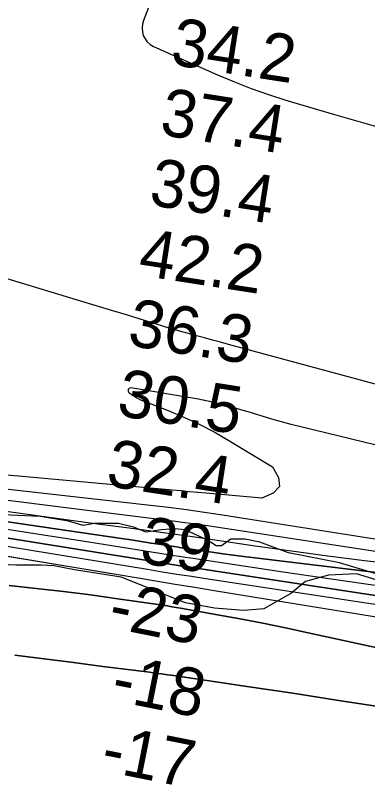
# Model space of a CAD drawing. Extents: x 3192986 to 3230865, y 867483 to 892886.
# Drawn here: x 3210569 to 3211065, y 879751 to 880841 of the extents above; entities that cross this region are included whole.
import ezdxf

# ---------------------------------------------------------------- set-up
doc = ezdxf.new("R2010")
doc.units = 0
for name, color, linetype in [('V-RIVR-EDGE', 7, 'Continuous'), ('V-RIVR-RANG', 7, 'Continuous'), ('V-SITE-VEGE', 7, 'Continuous'), ('V-TOPO-DPTH', 7, 'Continuous'), ('V-TOPO-MAJR', 7, 'Continuous'), ('V-TOPO-MINR', 7, 'Continuous'), ('V-TOPO-WATR', 7, 'Continuous')]:
    doc.layers.add(name, color=color, linetype=linetype)

msp = doc.modelspace()

# ---------------------------------------------------------------- linework, layer by layer
at = {"layer": 'V-RIVR-EDGE'}
for points in [[(3210859.2, 880094.2), (3210851.8, 880094.2), (3210839.7, 880102.5), (3210808.4, 880116.9), (3210793.2, 880118.3), (3210774.9, 880117), (3210753.2, 880113.6), (3210735.4, 880120.6), (3210714.5, 880125.8), (3210680.6, 880125.9), (3210664.5, 880122.9), (3210644.1, 880129.1), (3210604.1, 880135.7), (3210541.1, 880138.4)], [(3211076.9, 880055), (3211025.6, 880070.3), (3210953.5, 880084.4), (3210913.5, 880099.3), (3210892.7, 880103.7), (3210872.7, 880103.7), (3210859.2, 880094.2)]]:
    msp.add_lwpolyline(points, dxfattribs=at)
at = {"layer": 'V-SITE-VEGE'}
msp.add_lwpolyline([(3211090.9, 880042.3), (3211049.3, 880054.9), (3211010.1, 880052.9), (3210977.7, 880044), (3210957, 880027.2), (3210919.2, 880005.6), (3210890.2, 880003.5), (3210849.4, 880006.6), (3210808.6, 880014), (3210718, 880050.2), (3210652.3, 880060.6), (3210623.4, 880066.1), (3210605.5, 880067.2), (3210569.8, 880066.9), (3210528.1, 880069.2)], dxfattribs=at)
at = {"layer": 'V-TOPO-DPTH'}
for points in [[(3210112.9, 880193.6), (3210718.5, 880104.6), (3210732.4, 880102.6), (3210746.4, 880100.5), (3210760.3, 880098.3), (3210774.3, 880096.2), (3210798.9, 880092.4), (3210800.5, 880092.1), (3210803.8, 880091.6), (3210805.5, 880091.4), (3210831.6, 880087.4), (3210846.4, 880085.3), (3210861.1, 880083.2), (3210875.9, 880081.2), (3210890.7, 880079.4), (3211579, 879996.4), (3211581.2, 879996.2), (3211585.7, 879995.6), (3211588, 879995.3), (3211592.5, 879994.7), (3211594.8, 879994.3), (3211597, 879993.9), (3212032, 879904.4), (3212085, 879893.1)], [(3210112.9, 880193.6), (3210718.5, 880104.6), (3210732.4, 880102.6), (3210746.4, 880100.5), (3210760.3, 880098.3), (3210774.3, 880096.2), (3210798.9, 880092.4), (3210800.5, 880092.1), (3210803.8, 880091.6), (3210805.5, 880091.4), (3210831.6, 880087.4), (3210846.4, 880085.3), (3210861.1, 880083.2), (3210875.9, 880081.2), (3210890.7, 880079.4), (3211579, 879996.4), (3211581.2, 879996.2), (3211585.7, 879995.6), (3211588, 879995.3), (3211592.5, 879994.7), (3211594.8, 879994.3), (3211597, 879993.9), (3212032, 879904.4), (3212085, 879893.1)], [(3212100.7, 879932.9), (3212018.6, 879954.3), (3211575.3, 880022.3), (3211415.7, 880040.8), (3211330.7, 880051.1), (3211245.8, 880062), (3211161, 880073.8), (3211076.3, 880086.3), (3210839.6, 880122.3), (3210823.6, 880124.7), (3210807.6, 880126.9), (3210791.5, 880129.1), (3210775.5, 880131.1), (3210651.7, 880146.4), (3210573.7, 880156.1), (3210495.8, 880165.9)], [(3212273.2, 879751.3), (3211940.1, 879826.4), (3211878.8, 879840.2), (3211817.4, 879853.9), (3211756.1, 879867.5), (3211694.7, 879881), (3211644.4, 879892.1), (3211608.1, 879899.9), (3211571.8, 879907.4), (3211535.3, 879914.6), (3211498.9, 879921.5), (3211449.5, 879930.6), (3211388.3, 879941.7), (3211327.1, 879952.5), (3211265.8, 879963), (3211204.4, 879973.2), (3210849.3, 880031.1), (3210821.8, 880035.6), (3210794.3, 880040.1), (3210766.8, 880044.7), (3210739.3, 880049.2), (3210106, 880154.6)], [(3210517.9, 880111.9), (3210769.9, 880071.3), (3210784.1, 880069), (3210798.4, 880066.7), (3210812.6, 880064.5), (3210826.9, 880062.3), (3211177.7, 880009.1), (3211244.6, 879999.2), (3211311.6, 879989.8), (3211378.6, 879981), (3211445.7, 879972.5), (3211578.3, 879956.4), (3211579.1, 879956.3), (3211579.9, 879956.2), (3211584.1, 879955.6), (3211584.9, 879955.4), (3212313.1, 879797.1)], [(3212313.1, 879797.1), (3211584.9, 879955.4), (3211584.1, 879955.6), (3211579.9, 879956.2), (3211579.1, 879956.3), (3211578.3, 879956.4), (3211445.7, 879972.5), (3211378.6, 879981), (3211311.6, 879989.8), (3211244.6, 879999.2), (3211177.7, 880009.1), (3210826.9, 880062.3), (3210812.6, 880064.5), (3210798.4, 880066.7), (3210784.1, 880069), (3210769.9, 880071.3), (3210517.9, 880111.9)], [(3212273.2, 879751.3), (3211940.1, 879826.4), (3211878.8, 879840.2), (3211817.4, 879853.9), (3211756.1, 879867.5), (3211694.7, 879881), (3211644.4, 879892.1), (3211608.1, 879899.9), (3211571.8, 879907.4), (3211535.3, 879914.6), (3211498.9, 879921.5), (3211449.5, 879930.6), (3211388.3, 879941.7), (3211327.1, 879952.5), (3211265.8, 879963), (3211204.4, 879973.2), (3210849.3, 880031.1), (3210821.8, 880035.6), (3210794.3, 880040.1), (3210766.8, 880044.7), (3210739.3, 880049.2), (3210478.2, 880092.7)], [(3210560.5, 880038.3), (3210598.8, 880034.4), (3210637, 880030.1), (3210675.2, 880025.2), (3210713.3, 880019.9), (3210777, 880010.6), (3210783.3, 880009.7), (3210789.5, 880008.7), (3210795.7, 880007.7), (3210801.9, 880006.6), (3210853.6, 879997.4), (3210885.6, 879991.5), (3210917.6, 879985.3), (3210949.4, 879978.8), (3210981.3, 879972.1), (3211546, 879849.6)], [(3211546, 879849.6), (3210981.3, 879972.1), (3210949.4, 879978.8), (3210917.6, 879985.3), (3210885.6, 879991.5), (3210853.6, 879997.4), (3210801.9, 880006.6), (3210795.7, 880007.7), (3210789.5, 880008.7), (3210783.3, 880009.7), (3210777, 880010.6), (3210713.3, 880019.9), (3210675.2, 880025.2), (3210637, 880030.1), (3210598.8, 880034.4), (3210560.5, 880038.3)], [(3211544.4, 879792.6), (3211522, 879795.7), (3211499.7, 879799.2), (3211144.6, 879857.6), (3211083.1, 879867.6), (3211021.5, 879877.3), (3210959.9, 879886.7), (3210898.3, 879896), (3210791.7, 879911.7), (3210783.4, 879912.9), (3210775, 879914.1), (3210766.7, 879915.2), (3210758.3, 879916.3), (3210692.5, 879924.6), (3210651.2, 879929.9), (3210609.9, 879935.2), (3210568.7, 879940.6)], [(3210568.7, 879940.6), (3210609.9, 879935.2), (3210651.2, 879929.9), (3210692.5, 879924.6), (3210758.3, 879916.3), (3210766.7, 879915.2), (3210775, 879914.1), (3210783.4, 879912.9), (3210791.7, 879911.7), (3210898.3, 879896), (3210959.9, 879886.7), (3211021.5, 879877.3), (3211083.1, 879867.6), (3211144.6, 879857.6), (3211499.7, 879799.2), (3211522, 879795.7), (3211544.4, 879792.6)]]:
    msp.add_lwpolyline(points, dxfattribs=at)
at = {"layer": 'V-TOPO-MAJR'}
for points in [[(3210770.7, 880889.3), (3210749.6, 880834), (3210748.2, 880828.7), (3210747.6, 880823.4), (3210748.1, 880818.1), (3210749.4, 880812.8), (3210751.9, 880807.9), (3210755, 880803.7), (3210759, 880800.3), (3210763.6, 880797.5), (3210853.9, 880757.3), (3210877.5, 880747.4), (3210901.3, 880738.1), (3210925.4, 880729.8), (3210949.8, 880722), (3211018.6, 880701.7), (3211077.7, 880684.7)], [(3211190.4, 880290.8), (3210869.3, 880378), (3210858.1, 880381), (3210846.8, 880384), (3210835.6, 880387.1), (3210824.4, 880390.1), (3210813.2, 880393.2), (3210802, 880396.3), (3210790.9, 880399.6), (3210779.7, 880402.9), (3210763.9, 880407.8), (3210744.8, 880413.6), (3210725.8, 880419.4), (3210706.7, 880425.2), (3210687.7, 880430.9), (3210432, 880508.2)]]:
    msp.add_lwpolyline(points, dxfattribs=at)
at = {"layer": 'V-TOPO-MINR'}
for points in [[(3211835.7, 880051.7), (3210957.5, 880265), (3210943.8, 880268.8), (3210930.2, 880272.8), (3210916.7, 880276.8), (3210903.2, 880280.9), (3210896.9, 880282.9), (3210886.5, 880286), (3210876, 880289), (3210865.6, 880291.8), (3210855, 880294.4), (3210840.5, 880298), (3210837.2, 880298.7), (3210833.9, 880299.5), (3210830.6, 880300.1), (3210827.2, 880300.7), (3210732, 880316.6), (3210729.6, 880315.8), (3210728.2, 880314.6), (3210728.2, 880312.7), (3210729.2, 880310.3), (3210734.7, 880306.3), (3210740.4, 880302.7), (3210746.5, 880299.6), (3210752.7, 880296.9), (3210784.5, 880284.7), (3210806.5, 880275.6), (3210828.1, 880265.7), (3210849.1, 880254.7), (3210869.8, 880242.8), (3210931, 880205.6), (3210939.6, 880190.5), (3210941.2, 880177.7), (3210932.3, 880168.4), (3210916.4, 880161.3), (3210837.9, 880168.4), (3210826.1, 880169.4), (3210814.2, 880170.5), (3210802.4, 880171.6), (3210790.5, 880172.7), (3210350.8, 880212.6)], [(3212039.6, 879926.4), (3211960.5, 879943.7), (3211881.2, 879959.8), (3211579.1, 880014.5), (3211111.7, 880067.4), (3211060.5, 880073.4), (3211009.2, 880079.8), (3210958.1, 880086.7), (3210907, 880093.9), (3210818.4, 880106.8), (3210811.6, 880107.8), (3210804.8, 880108.7), (3210798, 880109.7), (3210791.2, 880110.6), (3210729.7, 880119), (3210692.2, 880124.1), (3210654.6, 880129.2), (3210617.1, 880134.4), (3210579.6, 880139.6), (3210103.3, 880206.1)], [(3212354.1, 879878.5), (3211585.8, 880029.7), (3211583.5, 880029.1), (3211581, 880029), (3211518.1, 880036.4), (3211484, 880040.7), (3211449.9, 880045.2), (3211415.9, 880050.1), (3211381.9, 880055.2), (3210860.8, 880137.6), (3210835.6, 880141.4), (3210810.3, 880145), (3210785, 880148.3), (3210759.7, 880151.3), (3210521.7, 880178)], [(3212100.7, 879932.9), (3212018.6, 879954.3), (3211575.3, 880022.3), (3211415.7, 880040.8), (3211330.7, 880051.1), (3211245.8, 880062), (3211161, 880073.8), (3211076.3, 880086.3), (3210839.6, 880122.3), (3210823.6, 880124.7), (3210807.6, 880126.9), (3210791.5, 880129.1), (3210775.5, 880131.1), (3210651.7, 880146.4), (3210573.7, 880156.1), (3210495.8, 880165.9)], [(3212273.2, 879751.3), (3211940.1, 879826.4), (3211878.8, 879840.2), (3211817.4, 879853.9), (3211756.1, 879867.5), (3211694.7, 879881), (3211644.4, 879892.1), (3211608.1, 879899.9), (3211571.8, 879907.4), (3211535.3, 879914.6), (3211498.9, 879921.5), (3211449.5, 879930.6), (3211388.3, 879941.7), (3211327.1, 879952.5), (3211265.8, 879963), (3211204.4, 879973.2), (3210849.3, 880031.1), (3210821.8, 880035.6), (3210794.3, 880040.1), (3210766.8, 880044.7), (3210739.3, 880049.2), (3210106, 880154.6)], [(3212254.4, 879783.6), (3211762.8, 879895.5), (3211732.2, 879902.4), (3211701.5, 879909.3), (3211670.8, 879916.1), (3211640.1, 879922.9), (3211578.9, 879936.3), (3211578.6, 879936.3), (3211577.9, 879936.4), (3211558.9, 879938.7), (3211549.3, 879939.9), (3211539.8, 879941.2), (3211530.2, 879942.6), (3211520.6, 879944), (3210837.5, 880047.8), (3210817, 880051), (3210796.4, 880054.2), (3210775.9, 880057.5), (3210755.4, 880060.8), (3210263.6, 880141.5)], [(3212175.6, 879850), (3211590.9, 879974.6), (3211589.4, 879974.9), (3211586.3, 879975.4), (3211581.7, 879976), (3211580.2, 879976.2), (3211578.6, 879976.4), (3211228.3, 880018.8), (3211156.8, 880027.8), (3211085.4, 880037.2), (3211014, 880047.2), (3210942.8, 880057.7), (3210816.2, 880076.9), (3210808.2, 880078.1), (3210800.3, 880079.3), (3210792.3, 880080.5), (3210784.4, 880081.8), (3210672.7, 880099.5), (3210608.9, 880109.5), (3210545, 880119.3)], [(3212313.1, 879797.1), (3211584.9, 879955.4), (3211584.1, 879955.6), (3211579.9, 879956.2), (3211579.1, 879956.3), (3211578.3, 879956.4), (3211445.7, 879972.5), (3211378.6, 879981), (3211311.6, 879989.8), (3211244.6, 879999.2), (3211177.7, 880009.1), (3210826.9, 880062.3), (3210812.6, 880064.5), (3210798.4, 880066.7), (3210784.1, 880069), (3210769.9, 880071.3), (3210517.9, 880111.9)], [(3211546, 879849.6), (3210981.3, 879972.1), (3210949.4, 879978.8), (3210917.6, 879985.3), (3210885.6, 879991.5), (3210853.6, 879997.4), (3210801.9, 880006.6), (3210795.7, 880007.7), (3210789.5, 880008.7), (3210783.3, 880009.7), (3210777, 880010.6), (3210713.3, 880019.9), (3210675.2, 880025.2), (3210637, 880030.1), (3210598.8, 880034.4), (3210560.5, 880038.3)], [(3210568.7, 879940.6), (3210609.9, 879935.2), (3210651.2, 879929.9), (3210692.5, 879924.6), (3210758.3, 879916.3), (3210766.7, 879915.2), (3210775, 879914.1), (3210783.4, 879912.9), (3210791.7, 879911.7), (3210898.3, 879896), (3210959.9, 879886.7), (3211021.5, 879877.3), (3211083.1, 879867.6), (3211144.6, 879857.6), (3211499.7, 879799.2), (3211522, 879795.7), (3211544.4, 879792.6)]]:
    msp.add_lwpolyline(points, dxfattribs=at)
at = {"layer": 'V-TOPO-WATR'}
msp.add_lwpolyline([(3212085, 879893.1), (3212032, 879904.4), (3211597, 879993.9), (3211594.8, 879994.3), (3211592.5, 879994.7), (3211588, 879995.3), (3211585.7, 879995.6), (3211581.2, 879996.2), (3211579, 879996.4), (3210890.7, 880079.4), (3210875.9, 880081.2), (3210861.1, 880083.2), (3210846.4, 880085.3), (3210831.6, 880087.4), (3210805.5, 880091.4), (3210803.8, 880091.6), (3210800.5, 880092.1), (3210798.9, 880092.4), (3210774.3, 880096.2), (3210760.3, 880098.3), (3210746.4, 880100.5), (3210732.4, 880102.6), (3210718.5, 880104.6), (3210112.9, 880193.6)], dxfattribs=at)

# ---------------------------------------------------------------- texts
at = {"layer": 'V-RIVR-RANG'}
for s, rotation, p in [('34.2', 351.1683, (3210786, 880772.3)), ('37.4', 351.1683, (3210770.9, 880673.4)), ('39.4', 351.1683, (3210755.8, 880574.6)), ('42.2', 351.1683, (3210740.7, 880475.7)), ('36.3', 351.1683, (3210725.6, 880376.8)), ('30.5', 351.1683, (3210710.5, 880278)), ('32.4', 351.1683, (3210695.4, 880179.1)), ('39', 351.1683, (3210742.8, 880070.6)), ('-23', 348.7144, (3210698, 879980)), ('-18', 348.7144, (3210702, 879877.4)), ('-17', 348.7144, (3210687.5, 879778.4))]:
    msp.add_text(s, height=67, rotation=rotation, dxfattribs=at).set_placement(p)

doc.saveas('drawing.dxf')
